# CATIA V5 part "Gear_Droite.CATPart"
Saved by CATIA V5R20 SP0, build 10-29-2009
Part number: Pièce1
Bounding box of the stored display mesh (mm): x -14.825 to 18.25, y -12.496 to 12.496, z -18 to 15.7
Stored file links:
  C:\Users\Admin\Desktop\Gear Droite.CATPart
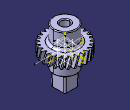
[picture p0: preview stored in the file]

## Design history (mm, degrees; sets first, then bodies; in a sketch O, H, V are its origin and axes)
Body1 (main body)
  Sketch1 on xy-plane, origin (0, 0, 0), H (1, 0, 0), V (0, 1, 0)
  Sketch2 on zx-plane, origin (0, 0, 0), H (-1, 0, 0), V (0, 0, 1)
    line L1 (0, 0) -> (1.2812, 4.4681)
    angle L1 V = 16
  Sketch3 on xy-plane, origin (0, 0, 0), H (1, 0, 0), V (0, 1, 0)
    circle A1 centre (0, 0) radius 10.75
    radius A1 = 10.75
  Pad1: profile Sketch3, direction (0, 0, 1), length 6.1
  Plane1: type Offset, RefPlane xy-plane, Offset 3.05
  Sketch4 on Plane1, origin (0, 0, 3.05), H (1, 0, 0), V (0, 1, 0)
    line L1 (0, 4.9753) -> (0, -6.0734)
    point P1 (0, 4.9753)
    line L2 (-14.8253, 0) -> (18.2495, 0)
    point P3 (-14.8253, 0)
    coincidence: P1 V, P3 H
    vertical: L1 V
    horizontal: L2 H
  Plane2: type Angle, RefPlane Plane1, Direction Sketch4.L2, Angle -15.6
  Sketch5 on Plane2, origin (0, -0.8097, 3.2761), H (1, 0, 0), V (0, 0.9632, -0.2689)
    point P1 (0, -9.9093)
    construction circle A1 centre (-0.013, 0.8407) radius 10.75
    construction line L1 through (0, 0.8407) direction (0, -1)
    construction line L2 through (0, 0.8407) direction (1, 0)
    point P2 (12.3622, 0.8407)
    axis line L3 (12.3622, 0.8407) -> (-13.4567, 0.8407)
    line L4 (12.437, 1.2157) -> (12.437, 0.4657)
    point P3 (10.737, 0.8407)
    point P4 (12.437, 1.2157)
    spline S1 through (12.437, 0.4657) (11.9519, 0.1717) (11.214, -0.0548) (10.6904, -0.1593)
    spline S2 through (12.437, 1.2157) (11.9519, 1.5097) (11.214, 1.7361) (10.6904, 1.8407)
    point P7 (10.6904, 1.8407)
    construction arc A2 centre (-0.013, 0.8407) radius 10.75 from (10.6904, -0.1593) to (10.6904, 1.8407) ccw
    reference projected line E1 (-14.8253, 0.8407) -> (18.2495, 0.8407) from Sketch4.L2
    reference projected line E2 (0, 5.6233) -> (0, -4.9974) from Sketch4.L1
    line L5 (10.6904, 1.8407) -> (9.804, 2.0177)
    point P10 (10.6904, 1.8407)
    line L6 (10.6904, -0.1593) -> (9.804, -0.3363)
    line L7 (9.804, 2.0177) -> (9.804, -0.3363)
    point P13 (12.437, 1.2157)
    point P14 (10.6904, 1.8407)
    point P15 (11.214, 1.7361)
    point P16 (11.214, -0.0548)
    distance P3 L4 = 1.7
    length L4 = 0.75
    radius A1 = 10.75
    coincidence: A1 P1, P1 L1, P2 L2, P3 A1, P3 L3, P14 P7, P4 P13, A2 A1, L3 E1, L1 E2, P14 P10, L5 P15, L6 P16
    vertical: L3 L2, L7 V
    horizontal: L4 L1
    symmetry: S2 S1 L3, P15 P16 L3
  Pad2: profile Sketch5, direction (0, 0.2689, 0.9632), up to end face of Pad1, opposite side up to start face of Pad1
  Sketch6 on yz-plane, origin (0, 0, 0), H (0, 1, 0), V (0, 0, 1)
    line L1 (0, 8.7327) -> (0, -6.8181)
    point P1 (0, 8.7327)
    coincidence: P1 V
    vertical: L1 V
  CircPattern1: of Pad2, instances 27, angular step 13.8462, axis from Sketch6.L1
  Sketch7 on face of CircPattern1, origin (0, 0, 6.1), H (1, 0, 0), V (0, 1, 0)
    circle A1 centre (0, 0) radius 7
    radius A1 = 7
  Pad3: profile Sketch7, direction (0, 0, 1), length 9.6
  Sketch8 on face of CircPattern1, origin (0, 0, 0), H (1, 0, 0), V (0, -1, 0)
    circle A1 centre (0, 0) radius 7
    radius A1 = 7
  Pad4: profile Sketch8, direction (0, 0, -1), length 8
  Sketch9 on end face of Pad4, origin (0, 0, -8), H (1, 0, 0), V (0, -1, 0)
    line L1 (-4.5, 4.5) -> (4.5, 4.5)
    line L2 (4.5, 4.5) -> (4.5, -4.5)
    line L3 (4.5, -4.5) -> (-4.5, -4.5)
    line L4 (-4.5, -4.5) -> (-4.5, 4.5)
    length L2 = 9
    length L3 = 9
    horizontal: L1 H, L3 H
    vertical: L2 V, L4 V
    symmetry: L2 L4 V, L1 L3 H
  Pad5: profile Sketch9, direction (0, 0, -1), length 10
  Sketch10 on yz-plane, origin (0, 0, 0), H (0, 1, 0), V (0, 0, 1)
    reference projected line E1 (7, -8) -> (-7, -8) from edge [face of Pad4 from Sketch8.A1 | end face of Pad4]
    reference projected line E4 (4.5, -18) -> (-4.5, -18) from edge [face of Pad5 from Sketch9.L2 | end face of Pad5]
    line L1 (-4.25, -18) -> (4.25, -18)
    point P9 (-4.25, -18)
    point P10 (4.25, -18)
    line L2 (-4.5, -8) -> (-4.25, -18)
    line L3 (4.5, -8) -> (4.25, -18)
    point P11 (-8.6782, -8)
    line L4 (-8.6782, -8) -> (-4.5, -8)
    line L5 (7.9099, -8) -> (7.9099, -20.4658)
    line L6 (7.9099, -20.4658) -> (-8.6782, -20.4658)
    line L7 (-8.6782, -20.4658) -> (-8.6782, -8)
    line L8 (4.5, -8) -> (7.9099, -8)
    length L1 = 8.5
    coincidence: P9 E4, P11 E1, L4 L8
    horizontal: L1 H, L4 H, L6 H, L8 H
    symmetry: P10 P9 V
    vertical: L5 V, L7 V
  Pocket1: profile Sketch10, direction (-1, 0, 0), length 10, mirrored extent
  Sketch11 on zx-plane, origin (0, 0, 0), H (-1, 0, 0), V (0, 0, 1)
    point P1 (-4.25, -18)
    line L1 (-4.25, -18) -> (4.25, -18)
    point P2 (4.25, -18)
    line L2 (-8.6782, -8) -> (-4.5, -8)
    line L3 (7.9099, -20.4658) -> (-8.6782, -20.4658)
    line L4 (7.9099, -8) -> (7.9099, -20.4658)
    line L5 (-8.6782, -20.4658) -> (-8.6782, -8)
    line L6 (4.5, -8) -> (7.9099, -8)
    projected line E1 (7, -8) -> (-7, -8) from edge [face of Pad4 from Sketch8.A1 | end face of Pad4]
    projected line E2 (-4.5, -8) -> (-4.5, -18) from edge [face of Pad5 from Sketch9.L2 | face of Pad5 from Sketch9.L3]
    projected line E3 (-4.5, -8) -> (-4.5, -18) from edge [face of Pad5 from Sketch9.L1 | face of Pad5 from Sketch9.L2]
    projected point E4 (-4.5, -18) from edge [face of Pad5 from Sketch9.L2 | end face of Pad5]
    line L7 (4.5, -8) -> (4.25, -18)
    line L8 (-4.5, -8) -> (-4.25, -18)
    length L1 = 8.5
    distance L1 L6 = 10
    horizontal: L1 H, L2 H, L3 H, L6 H
    symmetry: P2 P1 V
    vertical: L4 V, L5 V
    coincidence: L2 L6
  Pocket2: profile Sketch11, direction (0, -1, 0), length 10, mirrored extent
  Chamfer1: length 0.7, angle 45, on face of Pocket2 from Sketch11.L1
  Fillet1: radius 1, on edge [face of Pocket2 from Sketch11.L8 | face of Pocket1 from Sketch10.L3]; edge [face of Pocket1 from Sketch10.L2 | face of Pocket2 from Sketch11.L8]; edge [face of Pocket2 from Sketch11.L7 | face of Pocket1 from Sketch10.L2]; edge [face of Pocket1 from Sketch10.L3 | face of Pocket2 from Sketch11.L7]; edge [face of Chamfer1 | face of Chamfer1] (x4)
  Fillet2: radius 0.5, on face of Pocket2
  Fillet3: radius 0.5, on edge [face of Pad3 from Sketch7.A1 | end face of Pad3]
  Sketch12 on end face of Pad3, origin (0, 0, 15.7), H (1, 0, 0), V (0, 1, 0)
    circle A1 centre (0, 0) radius 2.7
    radius A1 = 2.7
  Pocket3: profile Sketch12, direction (0, 0, -1), through (limit type 3)
  Fillet4: radius 0.5, on face of Pocket3 from Sketch12.A1
  Fillet5: radius 1.5, on edge [face of CircPattern1 | face of Pad4 from Sketch8.A1]; edge [face of CircPattern1 | face of Pad3 from Sketch7.A1]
